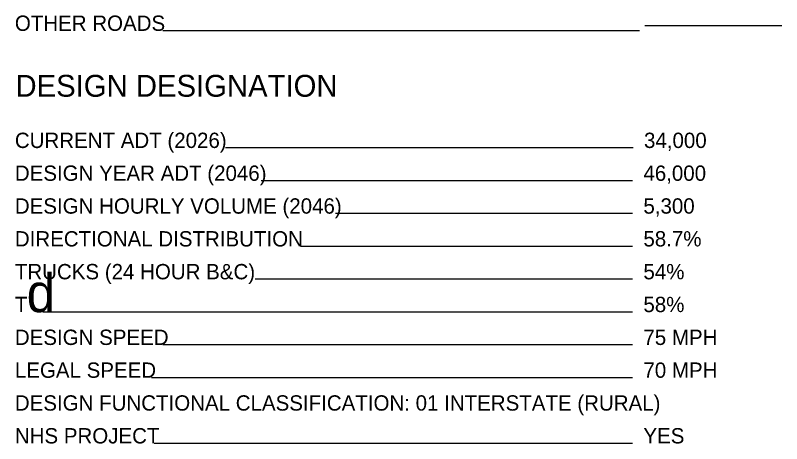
# Model space of a CAD drawing. Extents: x -21.9 to 47.3, y 14.1 to 48.7.
# Drawn here: x 2 to 9, y 33.84 to 37.75 of the extents above; entities that cross this region are included whole.
import ezdxf

# ---------------------------------------------------------------- set-up
doc = ezdxf.new("R2010")
doc.units = 0
doc.layers.add('SH_Data', color=7, linetype='Continuous')
doc.layers.add('SH_Text', color=7, linetype='Continuous')

msp = doc.modelspace()

# ---------------------------------------------------------------- linework, layer by layer
at = {"layer": 'SH_Data'}
for p, q in [((7.7, 37.6101), (3.3471, 37.6101)), ((9, 37.6557), (7.75, 37.6557)), ((7.6424, 36.5397), (3.9188, 36.5397)), ((7.6368, 36.2397), (4.2458, 36.2397)), ((7.6368, 35.9397), (4.9232, 35.9397)), ((7.6368, 35.6397), (4.6037, 35.6397)), ((7.6368, 35.3397), (4.1885, 35.3397)), ((7.6368, 35.0397), (2.2512, 35.0397)), ((7.6368, 34.7397), (3.346, 34.7397)), ((7.6368, 34.4397), (3.2422, 34.4397)), ((7.6368, 33.8397), (3.2669, 33.8397))]:
    msp.add_line(p, q, dxfattribs=at)

# ---------------------------------------------------------------- texts
msp.add_text('DESIGN DESIGNATION', height=0.2, dxfattribs=at).set_placement((2, 37.0081))
at = {"layer": 'SH_Text'}
for s, height, p in [('OTHER ROADS', 0.14, (1.9944, 37.6101)), ('CURRENT ADT (2026)', 0.14, (1.9944, 36.5397)), ('34,000', 0.14, (7.7424, 36.5397)), ('DESIGN YEAR ADT (2046)', 0.14, (1.9944, 36.2397)), ('46,000', 0.14, (7.7368, 36.2397)), ('DESIGN HOURLY VOLUME (2046)', 0.14, (1.9944, 35.9397)), ('5,300', 0.14, (7.7368, 35.9397)), ('DIRECTIONAL DISTRIBUTION', 0.14, (1.9944, 35.6397)), ('58.7%', 0.14, (7.7368, 35.6397)), ('TRUCKS (24 HOUR B&C)', 0.14, (1.9944, 35.3397)), ('54%', 0.14, (7.7368, 35.3397)), ('d', 0.35, (2.1019, 35.0397)), ('T', 0.14, (1.9944, 35.0397)), ('58%', 0.14, (7.7368, 35.0397)), ('DESIGN SPEED', 0.14, (1.9944, 34.7397)), ('75 MPH', 0.14, (7.7368, 34.7397)), ('LEGAL SPEED', 0.14, (1.9944, 34.4397)), ('70 MPH', 0.14, (7.7368, 34.4397)), ('DESIGN FUNCTIONAL CLASSIFICATION: 01 INTERSTATE (RURAL)', 0.14, (1.9944, 34.1397)), ('NHS PROJECT', 0.14, (1.9944, 33.8397)), ('YES', 0.14, (7.7368, 33.8397))]:
    msp.add_text(s, height=height, dxfattribs=at).set_placement(p)

doc.saveas('drawing.dxf')
